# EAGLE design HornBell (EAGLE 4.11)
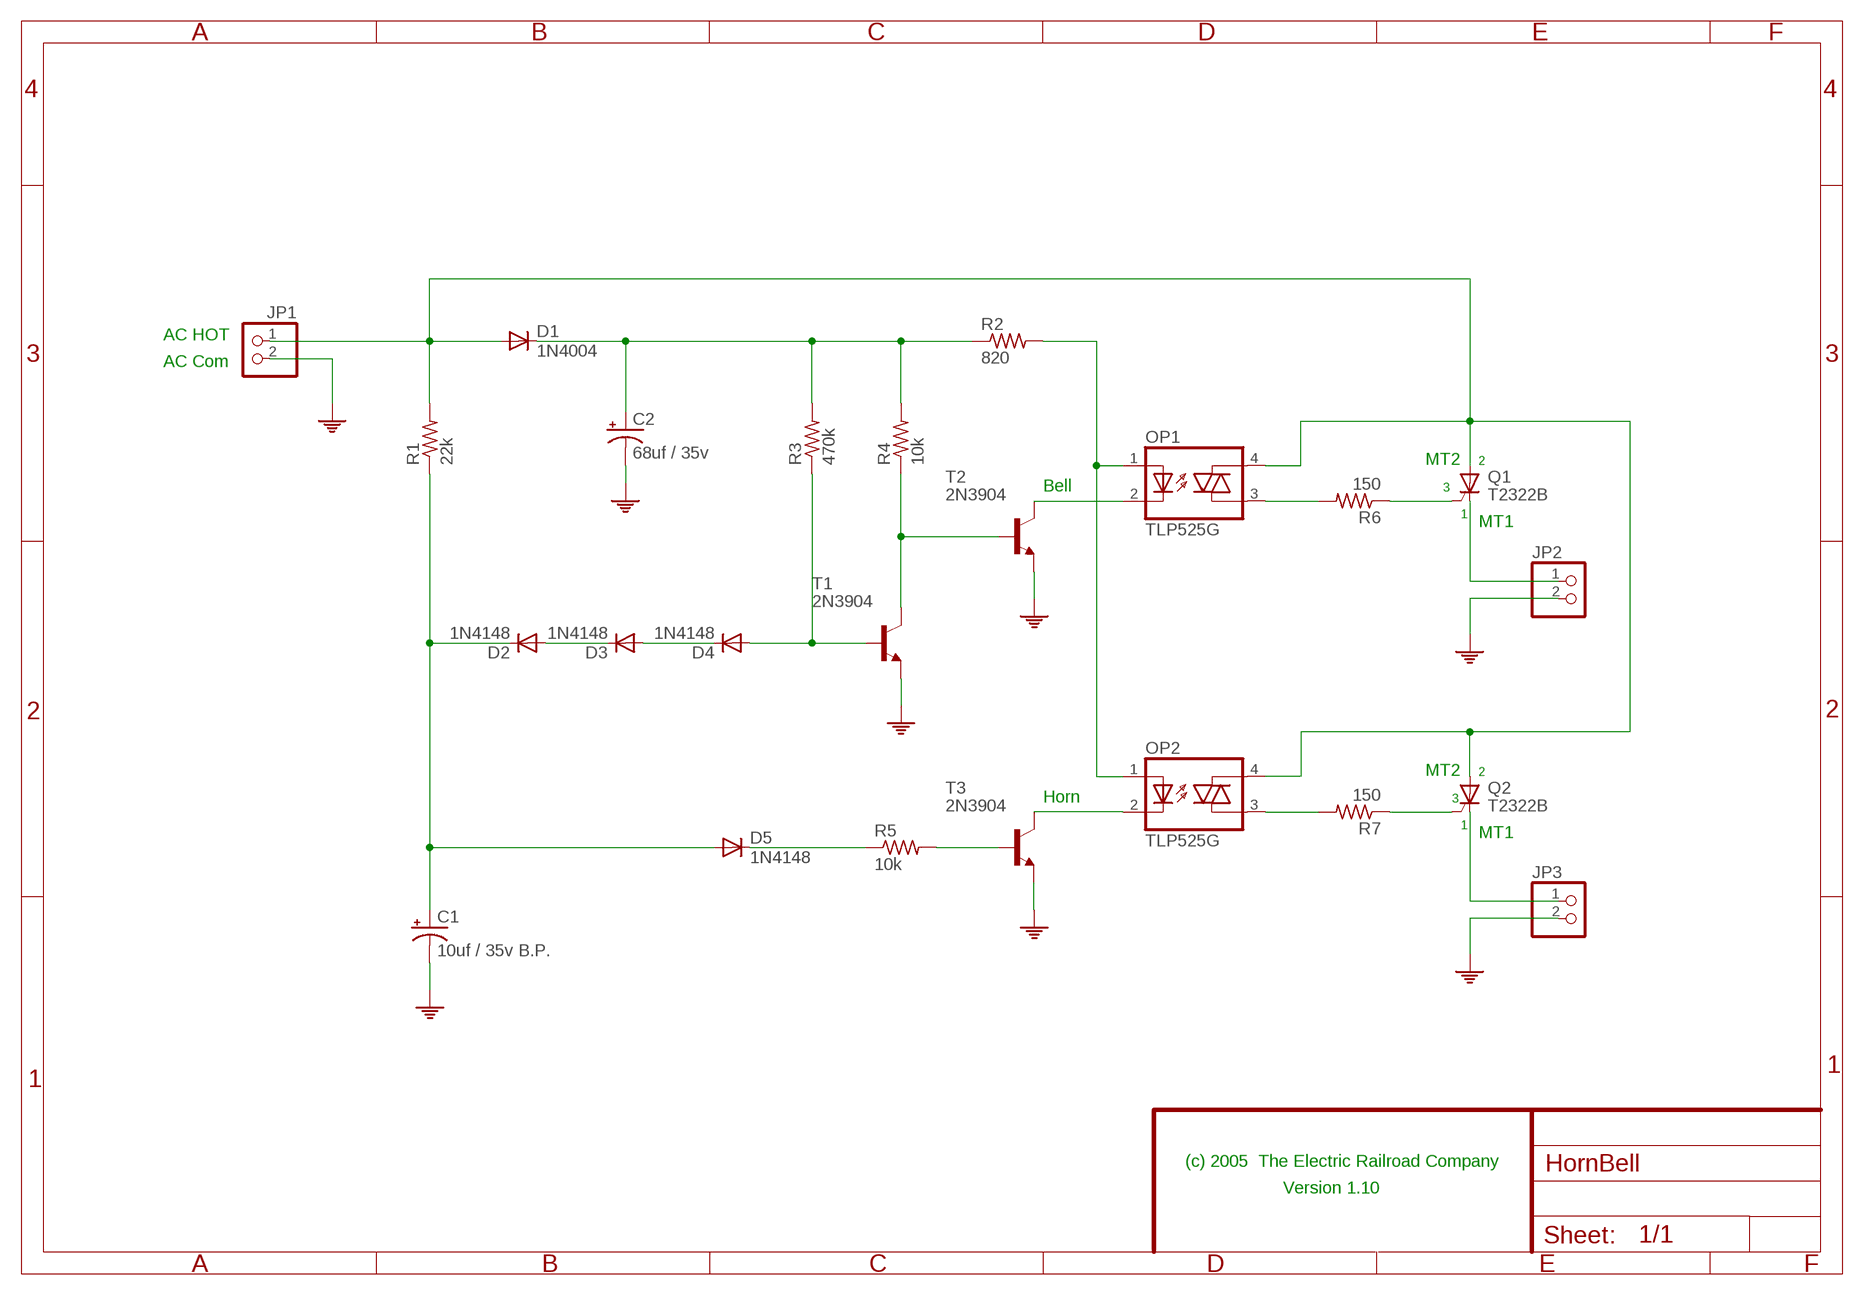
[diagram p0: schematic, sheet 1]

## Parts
C1  10uf / 35v B.P.  CPOL-USE2.5-6  [E2,5-6]
C2  68uf / 35v  CPOL-USE2.5-7  [E2,5-7]
D1  1N4004  DIODE-D-2.5  [D-2.5]
D2  1N4148  DIODE-D-2.5  [D-2.5]
D3  1N4148  DIODE-D-2.5  [D-2.5]
D4  1N4148  DIODE-D-2.5  [D-2.5]
D5  1N4148  DIODE-D-2.5  [D-2.5]
JP1  PINHD-1X2  [1X02]
JP2  PINHD-1X2  [1X02]
JP3  PINHD-1X2  [1X02]
OP1  TLP525G  IL420  [DIL04]
OP2  TLP525G  IL420  [DIL04]
Q1  T2322B  BT148  [SOT82S]
Q2  T2322B  BT148  [SOT82S]
R1  22k  R-US_0204/2V  [0204V]
R2  820  R-US_0204/2V  [0204V]
R3  470k  R-US_0204/2V  [0204V]
R4  10k  R-US_0204/2V  [0204V]
R5  10k  R-US_0204/2V  [0204V]
R6  150  R-US_0204/2V  [0204V]
R7  150  R-US_0204/2V  [0204V]
T1  2N3904  [TO92]
T2  2N3904  [TO92]
T3  2N3904  [TO92]

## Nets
N$1 [P24]: D1.A JP1.1 OP1.4(A2) OP2.4(A2) Q1.A Q2.A R1.2
N$2: OP1.2(C) T2.1(C)
N$3: OP1.1(A) OP2.1(A) R2.2
N$4: D5.C R5.1
N$5: R4.1 T1.1(C) T2.2(B)
N$6: D4.A R3.1 T1.2(B)
N$7: C1.+ D2.C D5.A R1.1
N$8: R5.2 T3.2(B)
N$9: Q2.G R7.1
N$10: OP2.2(C) T3.1(C)
N$13: OP1.3(A1) R6.2
N$14: C2.+ D1.C R2.1 R3.2 R4.2
N$15: D2.A D3.C
N$16: D3.A D4.C
N$17: OP2.3(A1) R7.2
N$18 [P24]: JP2.1 Q1.C
N$20 [P24]: JP3.1 Q2.C
PE [P24]: C1.- C2.- JP1.2 JP2.2 JP3.2 T1.3(E) T2.3(E) T3.3(E)
R5: Q1.G R6.1

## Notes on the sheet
- AC HOT
- AC Com
- MT2 | 2
- Bell | 3
- 1
- MT1
- MT2 | 2
- Horn | 3
- 1
- MT1
- (c) 2005  The Electric Railroad Company
- Version 1.10

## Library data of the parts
C1 C2 = rcl:CPOL-US: POLARIZED CAPACITOR, American symbol
D1-D5 = diode:DIODE-: DIODE
JP1-JP3 = pinhead:PINHD-1X2: PIN HEADER
OP1 OP2 = optocoupler-jz:IL420: SIEMENS OPTO COUPLER
Q1 Q2 = triac:BT148: THYRISTOR
R1-R7 = rcl:R-US_: RESISTOR, American symbol
T1-T3 = transistor:2N3904: NPN TRANSISTOR

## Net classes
1 P24: width 0.61 mm, drill 0.508 mm, clearance 0.61 mm

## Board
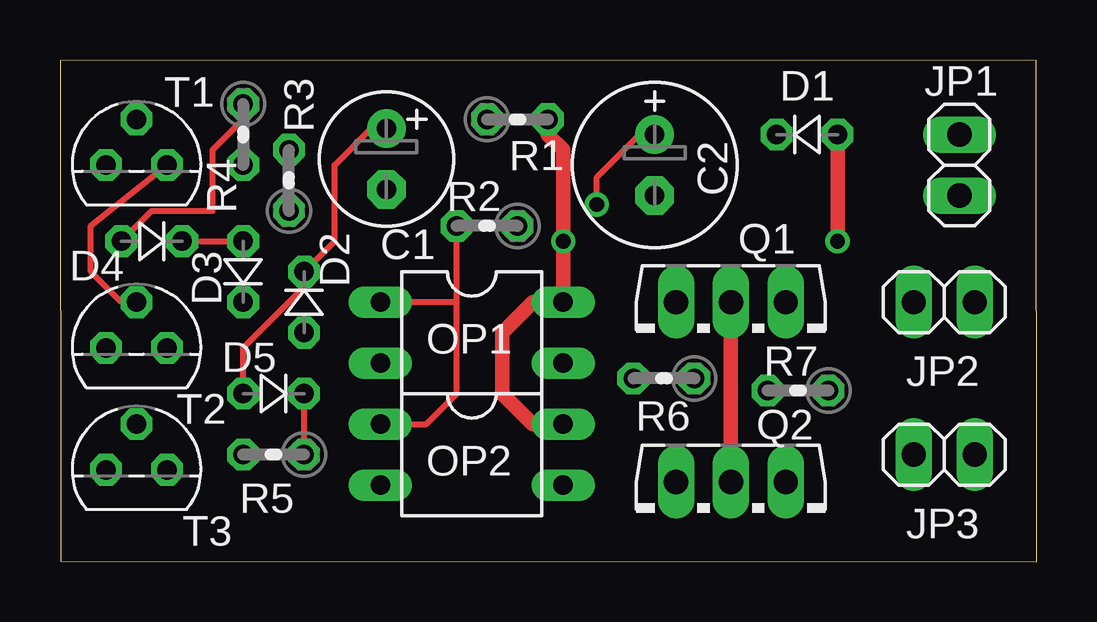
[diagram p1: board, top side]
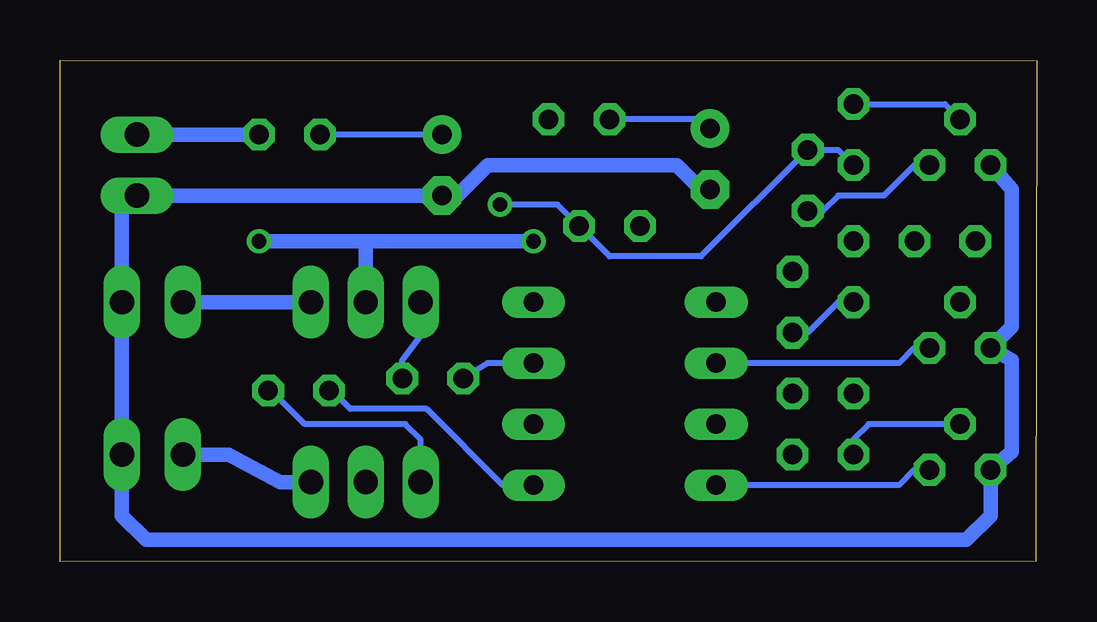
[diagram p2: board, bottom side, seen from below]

Size 40.69 x 20.91 mm. Coordinates in mm from the lower left corner, seen from the top.
Outline: 0.03,0.03 40.69,0 40.68,20.91 0,20.87 0.03,0.03
Copper layers (1*16): Top 0.035mm / dielectric 1.5mm / Bottom 0.035mm
Design rules "default": minimum track width 10mil, minimum drill 24mil, track to track 8mil, track to pad 8mil, pad to pad 8mil, via to via 8mil, smd to smd 8mil, copper to edge 20mil, drill to drill 8mil, minimum pad ring 10mil, minimum via ring 8mil, stop-mask expansion 4mil, vias tented up to drill 0mil, thermal gap 10mil

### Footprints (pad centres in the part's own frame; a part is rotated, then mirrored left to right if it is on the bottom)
E2,5-6 = drill 0.813 pad 1.6 round: + -1.27,0 | drill 0.813 pad 1.6 octagon: - 1.27,0
E2,5-7 = drill 0.813 pad 1.6 round: + -1.27,0 | drill 0.813 pad 1.6 octagon: - 1.27,0
D-2.5 = drill 0.813 octagon: A 1.27,0; C -1.27,0
1X02 = drill 1.016 long: 1 -1.27,0; 2 1.27,0
DIL04 = drill 0.813 long: 1 -1.27,-3.81; 2 1.27,-3.81; 3 1.27,3.81; 4 -1.27,3.81
SOT82S = drill 1.016 long: A 0,-1.27; C -2.286,-1.27; G 2.286,-1.27
0204V = drill 0.813 octagon: 1 -1.27,0; 2 1.27,0
TO92 = drill 0.813 octagon: 1 1.27,0; 2 0,1.905; 3 -1.27,0

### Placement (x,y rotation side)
C1  13.6,16.78 270 top
C2  24.78,16.53 270 top
D1  31.13,17.8 0 top
D2  10.17,10.82 270 top
D3  7.63,12.09 90 top
D4  3.82,13.36 180 top
D5  8.9,7.01 180 top
JP1  37.48,16.53 270 top
JP2  36.84,10.82 0 top
JP3  36.84,4.47 0 top
OP1  17.16,9.55 270 top
OP2  17.16,4.47 270 top
Q1  27.95,9.55 180 top
Q2  27.95,2.05 180 top
R1  19.06,18.44 0 top
R2  17.79,13.99 180 top
R3  7.63,17.8 270 top
R4  9.54,15.9 90 top
R5  8.9,4.47 180 top
R6  25.16,7.64 180 top
R7  30.75,7.13 180 top
T1  3.19,16.53 0 top
T2  3.19,8.91 0 top
T3  3.19,3.83 0 top

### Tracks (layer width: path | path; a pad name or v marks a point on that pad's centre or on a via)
N$1  (via drill 0.61)
  Top 0.61: v32.4,13.36 D1.A | OP2.4 19.7,5.74 18.43,7.01 18.43,9.55 19.7,10.82 OP1.4 v20.97,13.36 20.97,17.17 20.33,17.8 R1.2 | Q1.A Q2.A
  Bottom 0.61: D1.A JP1.1 | 27.95,13.36 v32.4,13.36 | v20.97,13.36 27.95,13.36 | 27.95,13.36 Q1.A
N$2
  Bottom 0.254: T2.1 5.09,8.91 5.73,8.28 OP1.2
N$3
  Top 0.254: 16.52,10.82 16.52,7.01 15.25,5.74 OP2.1 | 16.52,10.82 R2.2 | 16.52,10.82 OP1.1
N$4
  Top 0.254: R5.1 D5.C
N$5
  Top 0.254: T1.1 1.28,13.99 1.28,12.09 2.55,10.82 T2.2
  Bottom 0.254: R4.1 8.9,14.63 8.27,15.26 6.36,15.26 5.09,16.53 T1.1
N$6
  Top 0.254: D4.A 3.82,14.63 6.36,14.63 6.36,17.17 7.63,18.44 R3.1
  Bottom 0.254: T1.2 3.82,19.07 R3.1
N$7
  Top 0.254: D5.A 7.63,8.91 10.17,11.45 D2.C 11.44,13.36 11.44,16.53 12.97,18.05 C1.+
  Bottom 0.254: C1.+ 13.98,18.44 R1.1
N$8
  Bottom 0.254: T3.2 7,5.74 7.63,5.1 R5.2
N$9
  Bottom 0.254: R7.1 31.76,7.01 30.49,5.74 26.3,5.74 25.67,5.1 Q2.G
N$10
  Bottom 0.254: T3.1 5.09,3.83 5.73,3.2 OP2.2
N$13
  Bottom 0.254: R6.2 22.87,8.28 OP1.3
N$14  (via drill 0.61)
  Top 0.254: v22.36,14.88 22.36,16.02 24.14,17.8 C2.+
  Bottom 0.254: C2.+ D1.C | R3.2 8.27,17.17 R4.2 13.98,12.72 17.79,12.72 R2.1 19.95,14.88 v22.36,14.88
N$15
  Bottom 0.254: D3.C 8.27,10.82 9.54,9.55 D2.A
N$16
  Top 0.254: D4.C D3.A
N$17
  Bottom 0.254: OP2.3 22.24,3.2 25.41,6.37 28.59,6.37 29.22,7.01 R7.2
N$18
  Bottom 0.61: Q1.C JP2.1
N$20
  Bottom 0.61: Q2.C 31.51,3.32 33.67,4.47 JP3.1
PE
  Bottom 0.61: C1.- 13.98,15.51 15,16.53 22.87,16.53 24.14,15.26 C2.- JP1.2 38.11,14.63 JP2.2 JP3.2 38.11,1.93 37.1,0.91 2.93,0.91 1.92,1.93 T3.3 1.03,4.59 1.03,8.4 T2.3 1.03,9.8 1.03,15.51 T1.3
R5
  Bottom 0.254: R6.1 26.43,8.4 25.67,9.42 Q1.G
